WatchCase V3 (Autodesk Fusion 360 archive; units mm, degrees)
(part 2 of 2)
revolve "Revolve3" sketch "Sketch3" AlongAngle 360
extrude "Extrude4" cut sketch "Sketch3" profile of L6 L10 L11 L12 L13 distance 10
extrude "Extrude6" new body of existing geometry blind 5.6 bodies "Clamp Jaw 1"
sketch "Sketch5" plane through (0, 0, 0) normal (0, 1, 0) x axis (1, 0, 0)
  line L1 (20.8174, -7.0022) -> (-20, -7.0022)
  line L2 (-20, -1.4022) -> (20.8174, -1.4022)
  line L3 (6.8871, -1.4022) -> (4.8489, -7.0022)
  line L4 (0, -1.4022) -> (0, 0)
  line L5 (0, -7.0022) -> (0, -1.4022)
  line L6 (6.6743, -1.4022) -> (4.636, -7.0022)
  line L7 (0, -6.0022) -> (5, -6.0022)
  line L8 (-6.8871, -1.4022) -> (-4.8489, -7.0022)
  line L9 (-6.6743, -1.4022) -> (-4.636, -7.0022)
  line L10 (0, -6.0022) -> (-5, -6.0022)
  point P13 (5, -6.0022)
  point P14 (0, -6.0022)
  dimension "d47" distance L3 L6 = 0.2
  dimension "d48" angle L2 L6 = 70
  dimension "d49" distance P13 P14 = 5
  dimension "d50" distance L1 L7 = 1
extrude "Extrude7" cut sketch "Sketch5" profile of L1 L2 L3 L5 L6 L7 L8 L9 L10 distance 10 bodies "Clamp Jaw Center", "Clamp Jaws 2"
sketch "Sketch6" plane through (0, 0, 7.0022) normal (0, 0, 1) x axis (-1, 0, 0)
  line L1 (-4.8489, 5) -> (-4.8489, -5)
  line L2 (-19.1013, 5) -> (-4.8489, 5)
  line L3 (-4.8489, -5) -> (-19.1013, -5)
  line L4 (14, -2) -> (16, -2)
  line L5 (16, 2) -> (14, 2)
  line L6 (6.6743, -5) -> (-6.6743, -5)
  line L7 (0, -5) -> (0, 0)
  line L8 (0, 0) -> (14, 0)
  line L9 (16, 0) -> (14, 0)
  line L10 (-14, -2) -> (-16, -2)
  line L11 (-16, 2) -> (-14, 2)
  line L12 (1.7, -4) -> (1.7, -6.1)
  line L13 (-1.7, -4) -> (1.7, -4)
  line L14 (-1.7, -6.1) -> (-1.7, -4)
  line L15 (-1.9, -3.8) -> (1.9, -3.8)
  line L16 (-1.9, -6.1) -> (-1.9, -3.8)
  line L17 (1.9, -3.8) -> (1.9, -6.1)
  line L18 (1.7, 4) -> (1.7, 6.1)
  line L19 (1.9, 3.8) -> (1.9, 6.1)
  line L20 (-1.9, 6.1) -> (-1.9, 3.8)
  line L21 (-1.7, 6.1) -> (-1.7, 4)
  line L22 (-1.7, 4) -> (1.7, 4)
  line L23 (-1.9, 3.8) -> (1.9, 3.8)
  arc A1 centre (-19.1697, 3.3264) radius 1.6 clockwise from (-20.7691, 3.3723) to (-19.4506, 4.9016)
  arc A2 centre (96.8326, 0) radius 117.65 clockwise from (-20.7691, -3.3723) to (-20.7691, 3.3723)
  arc A3 centre (-19.1697, -3.3264) radius 1.6 clockwise from (-19.4506, -4.9016) to (-20.7691, -3.3723)
  arc A4 centre (14, 0) radius 2 clockwise from (14, -2) to (14, 2)
  arc A5 centre (16, 0) radius 2 clockwise from (16, 2) to (16, -2)
  circle C1 centre (15, 0) radius 1.95
  arc A6 centre (-14, 0) radius 2 clockwise from (-14, 2) to (-14, -2)
  arc A7 centre (-16, 0) radius 2 clockwise from (-16, -2) to (-16, 2)
  circle C2 centre (-15, 0) radius 1.95
  circle C3 centre (0, 0) radius 1.75
  arc A8 centre (0, -6.1) radius 1.7 clockwise from (1.7, -6.1) to (-1.7, -6.1)
  arc A9 centre (0, -6.1) radius 1.9 clockwise from (1.9, -6.1) to (-1.9, -6.1)
  arc A10 centre (0, 6.1) radius 1.7 clockwise from (-1.7, 6.1) to (1.7, 6.1)
  arc A11 centre (0, 6.1) radius 1.9 clockwise from (-1.9, 6.1) to (1.9, 6.1)
  arc A12 centre (-19.7754, 6.7228) radius 1.85 clockwise from (-19.1013, 5) to (-19.4506, 4.9016)
  arc A13 centre (-19.7754, -6.7228) radius 1.85 clockwise from (-19.4506, -4.9016) to (-19.1013, -5)
  point P13 (14, -2)
  point P16 (16, -2)
  point P1 (0, 0)
  point P21 (15, 0)
  point P32 (1.7, -6.1)
  dimension "d53" diameter A5 = 4
  dimension "d54" diameter C1 = 3.9 (= "d53 - 0.1 mm")
  dimension "d55" distance P13 P16 = 2
  dimension "d56" distance P1 P21 = 15
  dimension "d61" diameter C3 = 3.5
  dimension "d63" radius A8 = 1.7 (= "( 3.6 / 2 ) * 1 mm - 0.1 mm")
  dimension "d64" distance L6 P32 = 1.1
  dimension "d65" distance L8 L13 = 4
  dimension "d66" = 0.2
extrude "Extrude8" add sketch "Sketch6" profile of C1 C2 along normal blind 2
extrude "Extrude9" cut sketch "Sketch6" profile of A5 A4 L4 L5 C1 A6 L10 A7 C2 L11 along normal blind 7 and against normal blind 1
extrude "Extrude13" cut sketch "Sketch6" profile of C3 no distance stored
extrude "Extrude11" sketch "Sketch6" profile of L6 A8 L12 L14 A10 L18 L21 L22 to an object
extrude "Extrude16" cut sketch "Sketch6" profile of L6 A8 L12 L13 L14 L16 L15 L17 A9 A10 A11 L18 L19 L20 L21 L22 L23 to an object
combine "Combine1" bodies "Clamp Upper", "Clamp Jaw 1", "Clamp Jaw Center", "Clamp Jaws 2"
sketch "Sketch13" plane through (0, 0, 0) normal (0, 0, 1) x axis (-1, 0, 0)
  circle C1 centre (-33, 0) radius 2.025
  circle C2 centre (33, 0) radius 2.025
  circle C3 centre (-33, 0) radius 3.5
  circle C4 centre (33, 0) radius 3.5
  dimension "d133" diameter C3 = 7
extrude "Extrude21" add sketch "Sketch13" along normal blind 2.75
sketch "Sketch15" plane through (0, 0, 10) normal (0, 0, 1) x axis (-1, 0, 0)
  circle C1 centre (0, 0) radius 19
  circle C2 centre (0, 0) radius 3.6
  dimension "d139" diameter C1 = 38
extrude "Extrude23" cut sketch "Sketch15" against normal blind 1
sketch "Sketch14" plane through (0, 0, 8) normal (0, 0, 1) x axis (-1, 0, 0)
  circle C1 centre (0, 0) radius 3.5
  dimension "d136" diameter C1 = 7
extrude "Extrude22" add sketch "Sketch14" along normal blind 2.75
named bodies: "Clamp", "Clamp Upper", "Clamp Jaw 1", "Clamp Jaw Center", "Clamp Jaws 2"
